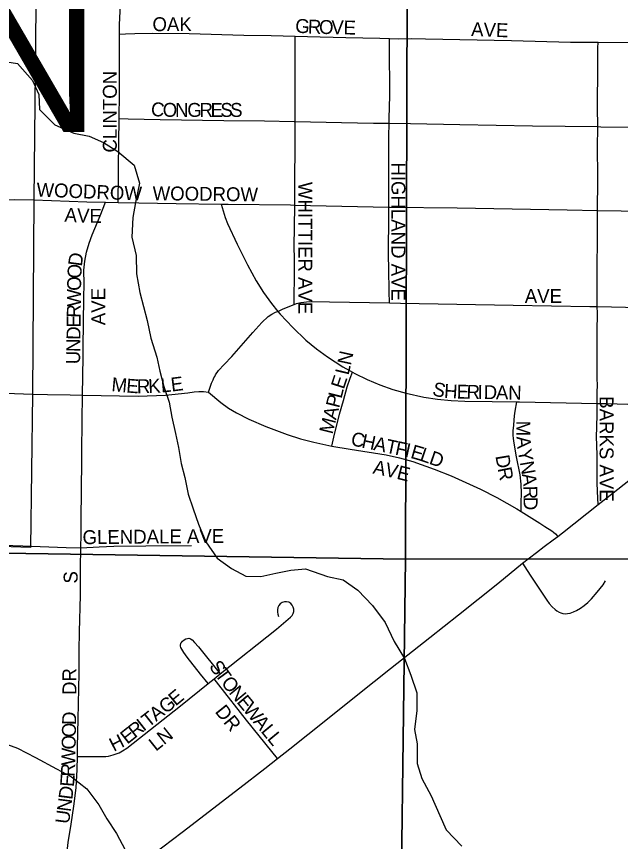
# Model space of a CAD drawing. Extents: x -9.1 to 34, y -3.1 to 22.
# Drawn here: x 3.961 to 4.372, y 18.579 to 19.14 of the extents above; entities that cross this region are included whole.
import ezdxf

# ---------------------------------------------------------------- set-up
doc = ezdxf.new("R2010")
doc.units = 0
for name, color, linetype in [('GM_X_City_Street', 7, 'Continuous'), ('GM_X_City_Street_Text', 7, 'Continuous'), ('GM_X_Corporation', 7, 'Continuous'), ('GM_X_Corporation_Text', 7, 'Continuous'), ('GM_X_Minor_River', 7, 'Continuous'), ('GM_X_Section', 7, 'Continuous'), ('GM_X_State_Route', 7, 'Continuous'), ('GM_X_Township_Subdivision', 7, 'Continuous')]:
    doc.layers.add(name, color=color, linetype=linetype)

msp = doc.modelspace()

# ---------------------------------------------------------------- linework, layer by layer
at = {"layer": 'GM_X_City_Street'}
for points in [[(4.03094, 19.12826), (4.03095, 19.13452), (4.0313, 19.14389), (4.03213, 19.21891), (4.03216, 19.24434)], [(4.03062, 19.07079), (4.03087, 19.08766), (4.03094, 19.12826)], [(4.03094, 19.12826), (4.0351, 19.1284), (4.04129, 19.12861), (4.05365, 19.12887), (4.07834, 19.12857), (4.11551, 19.12754), (4.13412, 19.12735), (4.15041, 19.12687)], [(4.15041, 19.12687), (4.15892, 19.12663), (4.18502, 19.126), (4.20813, 19.12544), (4.21474, 19.12526)], [(4.15046, 19.06875), (4.15046, 19.1092), (4.15043, 19.12172), (4.15041, 19.12687)], [(4.21442, 19.06748), (4.21447, 19.07083), (4.21482, 19.08632), (4.21474, 19.12046), (4.21474, 19.12526)], [(4.21474, 19.12526), (4.22064, 19.12509), (4.22991, 19.12525), (4.2392, 19.12506), (4.29762, 19.1238), (4.3379, 19.12274), (4.35657, 19.12264)], [(4.35643, 19.06522), (4.35627, 19.07815), (4.35637, 19.10626), (4.35652, 19.11872), (4.35657, 19.12264)], [(4.35657, 19.12264), (4.38127, 19.12251), (4.4051, 19.12192), (4.42691, 19.12157), (4.46688, 19.12069), (4.47084, 19.1206), (4.47341, 19.12055)], [(4.02998, 19.0136), (4.03002, 19.01638), (4.03025, 19.0302), (4.03014, 19.03766), (4.03062, 19.07079)], [(4.03062, 19.07079), (4.03683, 19.07065), (4.05851, 19.07016), (4.10181, 19.06948), (4.12967, 19.06912), (4.14982, 19.06876), (4.15046, 19.06875)], [(4.15015, 19.01188), (4.15019, 19.01521), (4.15049, 19.06533), (4.15046, 19.06875)], [(4.15046, 19.06875), (4.18199, 19.06812), (4.20368, 19.0676), (4.21442, 19.06748)], [(4.21425, 19.01037), (4.2141, 19.02432), (4.21427, 19.03673), (4.21421, 19.05845), (4.21442, 19.06748)], [(4.21442, 19.06748), (4.22887, 19.06732), (4.26251, 19.06669), (4.31189, 19.06587), (4.35643, 19.06522)], [(4.35627, 19.00821), (4.35652, 19.02878), (4.35611, 19.0538), (4.35624, 19.0567), (4.35647, 19.05937), (4.35649, 19.06254), (4.35643, 19.06522)], [(4.35643, 19.06522), (4.35842, 19.06519), (4.39555, 19.06464), (4.4675, 19.06317), (4.47243, 19.06307)], [(3.97257, 19.01533), (4.00875, 19.014), (4.02143, 19.01373)], [(4.00569, 18.88258), (4.00609, 18.90865), (4.00623, 18.91485), (4.00665, 18.94882), (4.00679, 18.95828), (4.0067, 18.96759), (4.00729, 18.97376), (4.00846, 18.97985), (4.01017, 18.98581), (4.0123, 18.99164), (4.01776, 19.00456), (4.02143, 19.01373)], [(4.02143, 19.01373), (4.02998, 19.0136)], [(4.02998, 19.0136), (4.04409, 19.01337), (4.06945, 19.01293), (4.10015, 19.01254)], [(4.10015, 19.01254), (4.10148, 19.00787), (4.10281, 19.0033), (4.10441, 18.99924), (4.11096, 18.98513), (4.11797, 18.97123), (4.12396, 18.96032), (4.12893, 18.95242), (4.13433, 18.94479), (4.13866, 18.93952)], [(4.10015, 19.01254), (4.10486, 19.01248), (4.14734, 19.01193), (4.15015, 19.01188)], [(4.1497, 18.94419), (4.14981, 18.94991), (4.15003, 18.96253), (4.14992, 18.97491), (4.14986, 18.98403), (4.14997, 18.99647), (4.15015, 19.01188)], [(4.15015, 19.01188), (4.21425, 19.01037)], [(4.21469, 18.9452), (4.2145, 18.95295), (4.21411, 18.96846), (4.21392, 18.97776), (4.2143, 19.0057), (4.21425, 19.01037)], [(4.21425, 19.01037), (4.21503, 19.01034), (4.26079, 19.00987), (4.33557, 19.00852), (4.35627, 19.00821)], [(4.35606, 18.94276), (4.35598, 18.95078), (4.35591, 18.96327), (4.35624, 18.99449), (4.35622, 19.00386), (4.35627, 19.00821)], [(4.35627, 19.00821), (4.38849, 19.00769), (4.44449, 19.00653), (4.47186, 19.00573)], [(4.1497, 18.94419), (4.15139, 18.94489), (4.15425, 18.94561), (4.16031, 18.94611), (4.21469, 18.9452)], [(4.21469, 18.9452), (4.21469, 18.9452), (4.22223, 18.94508), (4.29872, 18.94379), (4.35086, 18.94288), (4.35606, 18.94276)], [(4.09143, 18.88449), (4.0925, 18.88792), (4.09351, 18.89069), (4.09458, 18.89298), (4.09514, 18.89417), (4.09568, 18.89512), (4.09635, 18.89628), (4.09839, 18.89918), (4.10212, 18.90337), (4.10725, 18.90879), (4.12161, 18.92508), (4.12781, 18.93198), (4.13216, 18.9361), (4.13451, 18.93764), (4.13715, 18.93887), (4.13866, 18.93952)], [(4.13866, 18.93952), (4.14239, 18.94115), (4.1497, 18.94419)], [(4.13866, 18.93952), (4.14023, 18.93757), (4.14876, 18.92851), (4.15779, 18.91993), (4.16492, 18.91391), (4.17252, 18.90852), (4.18298, 18.90178), (4.18936, 18.89814)], [(4.35598, 18.87682), (4.35606, 18.88537), (4.35608, 18.88847), (4.35595, 18.89469), (4.35588, 18.90402), (4.35587, 18.91026), (4.35587, 18.91962), (4.35603, 18.92582), (4.35608, 18.93829), (4.35606, 18.94276)], [(4.35606, 18.94276), (4.38497, 18.94205), (4.4665, 18.94095), (4.47189, 18.94088)], [(4.17529, 18.84787), (4.17682, 18.85398), (4.18072, 18.86954), (4.18326, 18.87882), (4.18588, 18.88806), (4.18796, 18.89408), (4.18936, 18.89814)], [(4.18936, 18.89814), (4.19108, 18.89715), (4.19947, 18.89305), (4.2081, 18.88948), (4.21691, 18.88643), (4.22589, 18.88389), (4.23805, 18.88119), (4.24726, 18.87965), (4.25654, 18.87874), (4.26586, 18.87833), (4.28447, 18.87807), (4.30118, 18.87796)], [(3.97171, 18.88312), (3.98197, 18.88303), (3.99739, 18.8827), (4.00569, 18.88258)], [(4.00569, 18.88258), (4.04367, 18.88189), (4.06214, 18.88245), (4.07745, 18.88417), (4.08165, 18.88484), (4.08481, 18.88504), (4.08803, 18.88498), (4.09143, 18.88449)], [(4.09143, 18.88449), (4.09998, 18.87746), (4.10509, 18.87373), (4.11045, 18.8704), (4.11884, 18.86608), (4.13038, 18.86113), (4.14507, 18.85567), (4.15405, 18.85285), (4.16316, 18.85049), (4.17529, 18.84787)], [(4.00453, 18.7786), (4.00478, 18.78766), (4.0048, 18.80317), (4.00498, 18.81248), (4.00536, 18.8435), (4.00541, 18.86522), (4.00569, 18.88258)], [(4.30416, 18.80335), (4.30429, 18.80938), (4.30443, 18.81567), (4.3042, 18.82196), (4.30346, 18.82819), (4.30108, 18.84053), (4.29943, 18.84977), (4.29903, 18.85301), (4.29878, 18.85532), (4.29887, 18.85816), (4.29915, 18.86215), (4.29944, 18.86546), (4.2998, 18.86848), (4.30025, 18.87155), (4.30118, 18.87796)], [(4.30118, 18.87796), (4.30313, 18.87795), (4.35598, 18.87682)], [(4.3567, 18.80803), (4.35621, 18.81684), (4.35586, 18.82307), (4.35592, 18.8418), (4.35558, 18.85427), (4.35581, 18.86051), (4.35591, 18.86985), (4.35598, 18.87609), (4.35598, 18.87682)], [(4.35598, 18.87682), (4.36225, 18.87669), (4.40581, 18.8755), (4.42479, 18.87506), (4.42923, 18.87482), (4.43287, 18.87454), (4.43717, 18.87388), (4.44042, 18.8731)], [(4.17529, 18.84787), (4.17541, 18.84785), (4.18777, 18.84581), (4.2124, 18.8418), (4.22151, 18.83989), (4.23044, 18.83733), (4.24511, 18.83214), (4.25669, 18.82751), (4.27656, 18.81854), (4.28762, 18.81281), (4.3012, 18.8052), (4.30416, 18.80335)], [(4.30416, 18.80335), (4.31705, 18.7953), (4.32039, 18.79315), (4.32506, 18.79014), (4.32616, 18.78923), (4.32751, 18.78813), (4.32911, 18.78636)], [(3.97093, 18.77975), (3.99454, 18.7788), (4.00453, 18.7786)], [(4.00231, 18.63659), (4.00235, 18.63904), (4.00234, 18.64324), (4.0027, 18.66197), (4.00337, 18.6932), (4.00342, 18.7088), (4.00362, 18.72129), (4.00438, 18.74626), (4.00436, 18.7525), (4.00436, 18.76499), (4.00453, 18.7786)], [(4.00453, 18.7786), (4.01711, 18.7793), (4.02715, 18.77978), (4.04889, 18.78003), (4.07993, 18.78014)], [(4.30525, 18.76806), (4.30832, 18.76324), (4.31083, 18.75927), (4.3217, 18.74297), (4.3234, 18.74069), (4.3254, 18.73849), (4.32736, 18.73651), (4.32857, 18.73562), (4.33003, 18.73473), (4.33116, 18.73424), (4.3327, 18.73392), (4.33448, 18.73376), (4.33586, 18.73384), (4.33748, 18.73409), (4.33991, 18.7349), (4.34187, 18.73598), (4.34461, 18.73758), (4.34722, 18.73936), (4.34961, 18.74143), (4.35206, 18.74389), (4.35603, 18.74842), (4.35999, 18.75345), (4.36168, 18.75607)], [(4.09949, 18.69274), (4.13776, 18.72329), (4.14727, 18.7313), (4.14837, 18.73245), (4.14908, 18.73377), (4.14951, 18.7353), (4.14956, 18.73673), (4.1492, 18.73824), (4.14849, 18.73964), (4.1475, 18.74075), (4.14621, 18.74149), (4.14465, 18.74186), (4.14309, 18.74182), (4.14153, 18.74143), (4.14032, 18.74054), (4.13933, 18.73935), (4.13873, 18.73798), (4.13847, 18.73647), (4.13853, 18.73488), (4.13875, 18.73335), (4.13903, 18.73182)], [(4.09118, 18.68616), (4.08605, 18.69264), (4.07686, 18.70426), (4.07462, 18.70735), (4.07322, 18.70956), (4.07269, 18.71066), (4.07242, 18.7116), (4.07239, 18.71218), (4.07245, 18.71269), (4.07256, 18.71318), (4.07271, 18.71361), (4.07304, 18.71411), (4.07386, 18.71494), (4.07501, 18.71586), (4.07613, 18.71658), (4.07708, 18.71694), (4.0781, 18.71704), (4.07868, 18.71694), (4.07932, 18.71665), (4.08037, 18.71592), (4.08206, 18.71414), (4.08467, 18.71116), (4.09949, 18.69274)], [(4.09528, 18.68943), (4.09949, 18.69274)], [(4.00231, 18.63659), (4.00926, 18.63654), (4.01855, 18.63648), (4.0217, 18.63666), (4.02341, 18.63688), (4.02652, 18.63764), (4.03058, 18.63915), (4.03301, 18.64044), (4.03591, 18.64228), (4.07234, 18.67114), (4.09118, 18.68616)], [(4.09118, 18.68616), (4.09528, 18.68943)], [(4.1384, 18.63523), (4.13454, 18.64001), (4.11733, 18.66135), (4.09851, 18.68532), (4.09528, 18.68943)], [(4.00828, 18.5352), (4.00347, 18.54237), (4.00172, 18.54495), (4.00023, 18.5477), (3.99896, 18.55055), (3.99785, 18.55347), (3.99612, 18.55946), (3.99557, 18.56253), (3.99529, 18.56563), (3.99535, 18.57188), (3.996, 18.57809), (3.9981, 18.5904), (3.99988, 18.60277), (4.00132, 18.61517), (4.00215, 18.62763), (4.00231, 18.63659)]]:
    msp.add_lwpolyline(points, dxfattribs=at)
at = {"layer": 'GM_X_Corporation'}
msp.add_lwpolyline([(3.84232, 19.27891), (3.97523, 19.27787), (3.97257, 19.01533), (3.97172, 18.88312), (3.97024, 18.77889), (3.71873, 18.78737)], dxfattribs=at)
at = {"layer": 'GM_X_Minor_River'}
for points in [[(3.95141, 19.10987), (3.96159, 19.10818), (3.97161, 19.09663), (3.97598, 19.08708), (3.97657, 19.07683), (3.98699, 19.06642), (3.99975, 19.06089), (4.0103, 19.05881), (4.02006, 19.05447), (4.02979, 19.04824), (4.04097, 19.03895), (4.04455, 19.02675), (4.04169, 19.01353), (4.04001, 19.00332), (4.03941, 18.99006), (4.04223, 18.9775), (4.0424, 18.96499), (4.04484, 18.95243), (4.04982, 18.93339), (4.05227, 18.92122), (4.05621, 18.90826), (4.05833, 18.89874), (4.06118, 18.88846), (4.06478, 18.87778), (4.06651, 18.86751), (4.06897, 18.85647), (4.07108, 18.84696), (4.07279, 18.83593), (4.07528, 18.82641), (4.07774, 18.815), (4.08098, 18.80508), (4.08459, 18.79478), (4.08968, 18.78256), (4.09744, 18.77143), (4.10715, 18.76444), (4.1169, 18.75934), (4.1271, 18.75917), (4.13735, 18.76127), (4.14759, 18.76336), (4.15743, 18.76433), (4.17247, 18.75914), (4.18301, 18.75669), (4.19311, 18.74969), (4.20314, 18.73928), (4.21165, 18.72776), (4.21786, 18.71476), (4.22486, 18.70326), (4.22921, 18.69181), (4.23317, 18.67999), (4.23335, 18.66786), (4.23162, 18.65499), (4.23336, 18.64511), (4.23351, 18.63183), (4.23675, 18.62154), (4.24298, 18.60968), (4.24881, 18.59631), (4.25319, 18.58675), (4.26397, 18.57557)], [(3.94946, 18.64659), (3.96149, 18.64221), (3.97386, 18.63593), (3.9881, 18.6281), (3.99822, 18.62262), (4.00867, 18.61448), (4.01681, 18.60372), (4.02232, 18.59415), (4.02896, 18.58417), (4.03483, 18.57308)]]:
    msp.add_lwpolyline(points, dxfattribs=at)
at = {"layer": 'GM_X_Section'}
for points in [[(3.23473, 19.77259), (4.2285, 19.77719), (4.22542, 18.77097), (3.22195, 18.78578)], [(4.2285, 19.77719), (5.226, 19.77229), (5.22068, 18.771), (4.22542, 18.77097)], [(3.22195, 18.78578), (4.22542, 18.77097), (4.21254, 17.77165), (3.20939, 17.77812)], [(4.22542, 18.77097), (5.22068, 18.771), (5.21493, 17.76405), (4.21254, 17.77165)]]:
    msp.add_lwpolyline(points, close=True, dxfattribs=at)
at = {"layer": 'GM_X_State_Route'}
for points in [[(4.31477, 18.77541), (4.31995, 18.7794), (4.32609, 18.78401), (4.32911, 18.78636), (4.3323, 18.78877), (4.3567, 18.80803), (4.36689, 18.81608), (4.39139, 18.83527), (4.40119, 18.8428), (4.40613, 18.84638), (4.42078, 18.85774), (4.42651, 18.86223), (4.44042, 18.8731), (4.45267, 18.88268), (4.47121, 18.89689), (4.49199, 18.91277), (4.50642, 18.92413), (4.51828, 18.93403), (4.52079, 18.93612), (4.5289, 18.94247), (4.53609, 18.94811), (4.56183, 18.96848), (4.58606, 18.98729)], [(4.02978, 18.55166), (4.05374, 18.57001), (4.07365, 18.58504), (4.11277, 18.6153), (4.12971, 18.62841), (4.1384, 18.63523), (4.14685, 18.64188), (4.17126, 18.6613), (4.1932, 18.6788), (4.21521, 18.69641), (4.24213, 18.7175), (4.26162, 18.73304), (4.28825, 18.75436), (4.30525, 18.76806), (4.31477, 18.77541)]]:
    msp.add_lwpolyline(points, dxfattribs=at)
at = {"layer": 'GM_X_Township_Subdivision'}
for points in [[(3.94754, 19.01526), (3.95973, 19.01557), (3.97257, 19.01533)], [(3.94644, 18.88394), (3.95946, 18.88353), (3.97171, 18.88312)], [(3.94432, 18.78066), (3.96522, 18.77996), (3.97093, 18.77975)]]:
    msp.add_lwpolyline(points, dxfattribs=at)

# ---------------------------------------------------------------- texts
at = {"layer": 'GM_X_City_Street_Text'}
for s, height, rotation, p in [('OAK', 0.00947, 0, (4.05335, 19.13021)), ('G', 0.00947, 355.3616, (4.1502, 19.12936)), ('R', 0.00947, 357.891, (4.15896, 19.12867)), ('O', 0.00947, 358.7542, (4.16661, 19.12838)), ('V', 0.00947, 358.7879, (4.17495, 19.1282)), ('E', 0.00947, 358.8012, (4.18328, 19.12803)), ('AVE', 0.00947, 358.0264, (4.27007, 19.12687)), ('CLINTON', 0.00947, 90, (4.02907, 19.04759)), ('C', 0.00947, 354.7968, (4.05199, 19.07268)), ('O', 0.00947, 359.3846, (4.06029, 19.07196)), ('N', 0.00947, 359.9929, (4.06873, 19.07187)), ('G', 0.00947, 359.9929, (4.07706, 19.07187)), ('R', 0.00947, 359.9941, (4.08539, 19.07187)), ('E', 0.00947, 359.9956, (4.09289, 19.07187)), ('S', 0.00947, 359.9956, (4.09956, 19.07187)), ('S', 0.00947, 359.9956, (4.10622, 19.07187)), ('HIGHLAND AVE', 0.0094697, 270, (4.21596, 19.04092)), ('WOODROW', 0.00947, 357.7404, (3.97429, 19.0177)), ('WOODROW', 0.00947, 359.2457, (4.05338, 19.01521)), ('WHITTIER AVE', 0.0094697, 270, (4.15263, 19.02759)), ('A', 0.00947, 356.7632, (3.99333, 19.00061)), ('V', 0.00947, 357.8535, (4.00185, 19.00013)), ('E', 0.00947, 359.5061, (4.01047, 18.99981)), ('D', 0.00947, 82.414, (4.00527, 18.9698)), ('O', 0.00947, 86.9171, (4.00484, 18.96168)), ('O', 0.00947, 89.227, (4.00473, 18.95345)), ('W', 0.00947, 89.2267, (4.00459, 18.94261)), ('AVE', 0.00947, 90, (4.02119, 18.93009)), ('AVE', 0.00947, 0, (4.30668, 18.94521)), ('R', 0.00947, 89.2339, (4.00449, 18.93511)), ('E', 0.00947, 89.2296, (4.0044, 18.92845)), ('D', 0.00947, 89.2131, (4.00429, 18.92011)), ('N', 0.00947, 89.2349, (4.00417, 18.91178)), ('U', 0.00947, 89.2349, (4.00406, 18.90345)), ('N', 0.00947, 77.6618, (4.18831, 18.90238)), ('L', 0.00947, 76.4452, (4.1867, 18.89568)), ('M', 0.00947, 354.9293, (4.02518, 18.8852)), ('L', 0.00947, 4.9424, (4.05939, 18.88427)), ('E', 0.00947, 7.0355, (4.0664, 18.88488)), ('E', 0.00947, 71.9192, (4.18353, 18.88604)), ('E', 0.00947, 355.6836, (4.03527, 18.8843)), ('R', 0.00947, 0.6053, (4.04279, 18.88377)), ('K', 0.00947, 2.6025, (4.05065, 18.88386)), ('S', 0.00947, 346.2354, (4.24327, 18.88256)), ('H', 0.00947, 356.5249, (4.25158, 18.88069)), ('E', 0.00947, 358.7763, (4.2603, 18.88017)), ('R', 0.00947, 359.008, (4.26701, 18.88003)), ('I', 0.00947, 358.9949, (4.27451, 18.8799)), ('D', 0.00947, 359.0244, (4.27868, 18.87983)), ('A', 0.00947, 358.9945, (4.28701, 18.87968)), ('N', 0.00947, 359.0244, (4.29535, 18.87954)), ('P', 0.00947, 75.812, (4.18031, 18.87328)), ('L', 0.00947, 75.8198, (4.18194, 18.87974)), ('BARKS AVE', 0.00947, 270, (4.35763, 18.88176)), ('A', 0.00947, 75.8116, (4.17827, 18.8652)), ('M', 0.00947, 75.8136, (4.17582, 18.85551)), ('M', 0.00947, 270.2003, (4.30092, 18.86508)), ('C', 0.00947, 348.0138, (4.18783, 18.84851)), ('H', 0.00947, 348.0153, (4.19517, 18.84695)), ('A', 0.00947, 348.0153, (4.20332, 18.84522)), ('T', 0.00947, 348.0048, (4.21147, 18.84349)), ('F', 0.00947, 348.0288, (4.21799, 18.84211)), ('I', 0.00947, 347.7984, (4.2245, 18.84073)), ('A', 0.00947, 275.0528, (4.301, 18.85421)), ('E', 0.00947, 344.1747, (4.22842, 18.83988)), ('L', 0.00947, 341.0466, (4.23471, 18.83811)), ('D', 0.00947, 340.8048, (4.241, 18.83595)), ('Y', 0.00947, 279.8887, (4.30185, 18.84504)), ('A', 0.00947, 348.0686, (4.20285, 18.82923)), ('D', 0.00947, 279.5522, (4.28671, 18.84107)), ('V', 0.00947, 347.1725, (4.21097, 18.82752)), ('E', 0.00947, 345.7849, (4.21904, 18.82568)), ('R', 0.00947, 281.3195, (4.28815, 18.83254)), ('N', 0.00947, 279.8827, (4.30328, 18.83683)), ('A', 0.00947, 277.5181, (4.30469, 18.82872)), ('R', 0.00947, 271.2385, (4.30576, 18.82073)), ('D', 0.00947, 270, (4.30593, 18.81329)), ('GLENDALE AVE', 0.0094697, 0.5448, (4.00579, 18.78104)), ('S', 0.00947, 90, (4.00239, 18.75426)), ('S', 0.00947, 305.6457, (4.09147, 18.69779)), ('T', 0.00947, 306.1494, (4.0954, 18.6923)), ('DR', 0.00947, 90, (4.00156, 18.67842)), ('O', 0.00947, 308.7219, (4.09962, 18.68655)), ('E', 0.00947, 39.694, (4.0691, 18.67052)), ('N', 0.00947, 309.5839, (4.10493, 18.67992)), ('G', 0.00947, 38.2261, (4.06235, 18.6652)), ('E', 0.00947, 309.6212, (4.11024, 18.6735)), ('A', 0.00947, 38.2261, (4.0558, 18.66004)), ('DR', 0.00947, 308.6563, (4.09549, 18.66697)), ('W', 0.00947, 309.5946, (4.11449, 18.66836)), ('D', 0.00947, 88.8634, (4.00132, 18.6579)), ('T', 0.00947, 38.2033, (4.05056, 18.65591)), ('O', 0.00947, 88.8853, (4.00116, 18.64957)), ('R', 0.00947, 38.235, (4.0414, 18.6487)), ('I', 0.00947, 38.2161, (4.04729, 18.65334)), ('A', 0.00947, 309.5817, (4.1214, 18.66001)), ('L', 0.00947, 309.6038, (4.12671, 18.65359)), ('E', 0.00947, 38.5763, (4.0362, 18.64455)), ('LN', 0.00947, 38.6634, (4.05564, 18.63973)), ('L', 0.00947, 309.6027, (4.13096, 18.64845)), ('O', 0.00947, 88.8893, (4.00099, 18.64124)), ('H', 0.00947, 26.8191, (4.02698, 18.63964)), ('W', 0.00947, 88.6939, (4.00075, 18.63037)), ('R', 0.00947, 87.2845, (4.00038, 18.62262)), ('E', 0.00947, 85.6216, (3.99986, 18.61568)), ('D', 0.00947, 82.6658, (3.99874, 18.60688)), ('N', 0.00947, 82.5639, (3.99766, 18.5986)), ('U', 0.00947, 82.5469, (3.99658, 18.59034))]:
    msp.add_text(s, height=height, rotation=rotation, dxfattribs=at).set_placement(p)
at = {"layer": 'GM_X_Corporation_Text'}
msp.add_text('MARION', height=0.094697, rotation=0, dxfattribs=at).set_placement((3.51088, 19.06148))

doc.saveas('drawing.dxf')
